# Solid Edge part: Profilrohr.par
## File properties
Username: ahadarics
Dokumentum tartalom típus: 0
Author: ahadarics
Last saved by: ahadarics
Revision: 77
Sűrűség: 0,000 kg/m^3
Pontosság: 0,990
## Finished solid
Body 1: solid body, 6 faces, 6 edges, 0 vertices.
  Faces by surface: cone 2, cylinder 2, plane 2
  Edges by curve: circle 6
Bounding box of the edges (mm): 21.270 x 21.270 x 57.000, from (-10.635, -10.635, -21) to (10.635, 10.635, 36).
Cylindrical faces by radius (mm): R10 x1, R10.635 x1
Conical faces (half-angle, radius in mm at the cone's reference point): 15 deg R10.067 x2
Planar faces by outward normal: +z 1, -z 1
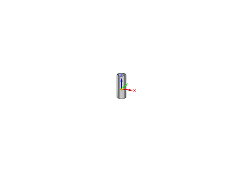
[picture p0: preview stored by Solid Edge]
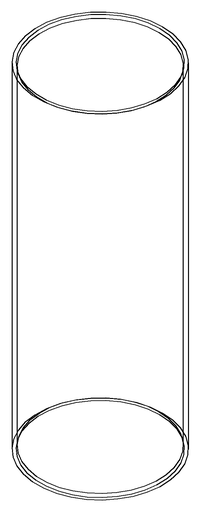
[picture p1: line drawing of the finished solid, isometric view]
